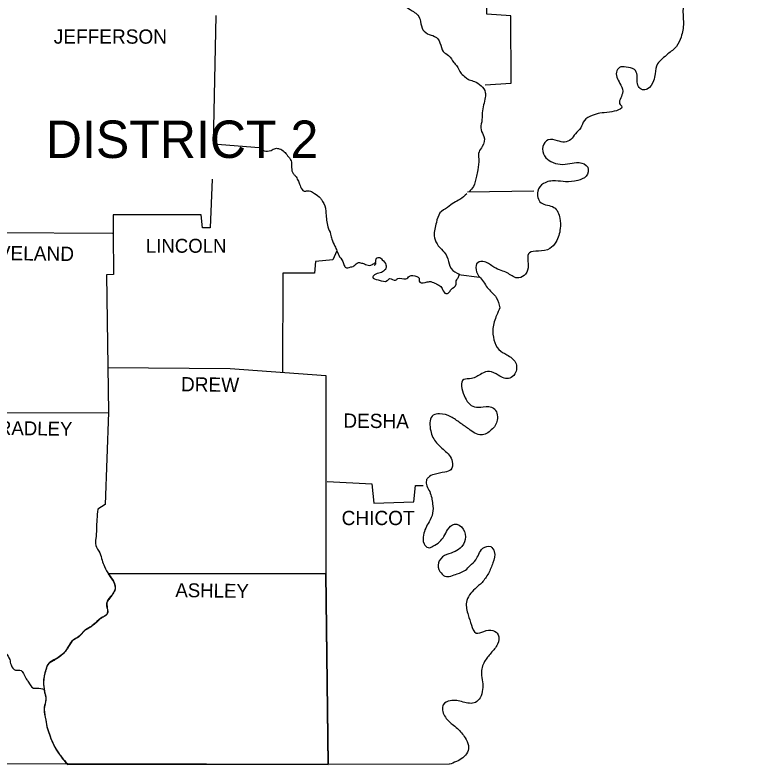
# Model space of a CAD drawing. Extents: x -42408 to 34530, y -43140 to 20491.
# Drawn here: x 3107 to 4217, y -9853 to -8719 of the extents above; entities that cross this region are included whole.
import ezdxf

# ---------------------------------------------------------------- set-up
doc = ezdxf.new("R2010")
doc.units = 0
for name, color, linetype in [('1', 7, 'Continuous'), ('2', 7, 'Continuous'), ('3', 7, 'Continuous'), ('S_MISC_BOUNDARY', 7, 'Continuous')]:
    doc.layers.add(name, color=color, linetype=linetype)

msp = doc.modelspace()

# ---------------------------------------------------------------- linework, layer by layer
at = {"layer": '1'}
msp.add_line((3791, -8986.4), (3891.1, -8984.9), dxfattribs=at)
for points in [[(3818, -8824.6), (3857.1, -8822.1), (3856.6, -8720.5), (3820.1, -8718), (3822.1, -8519.2), (3790.5, -8514.7), (3789.5, -8381), (4216.6, -8378)], [(3410.5, -8720), (3406.5, -8913.8), (3476.1, -8919.3)], [(3405, -8967.3), (3402, -9040.9), (3390.5, -9040.9), (3388.5, -9021.4), (3255.3, -9021.4), (3255.3, -9049.4)], [(3077.1, -9047.9), (3254.3, -9048.9)], [(3255.3, -9048.9), (3255.8, -9111.5), (3245.3, -9112), (3248.3, -9319.8)], [(3593.7, -9075.5), (3587.7, -9089), (3561.2, -9091.5), (3559.7, -9109.5), (3512.1, -9109.5), (3511.6, -9259.2)], [(3649.8, -9097.5), (3651.3, -9096), (3652.8, -9094.5), (3652.8, -9094.5)], [(3246.8, -9251.7), (3432.5, -9253.2), (3576.7, -9264.2)], [(3576.7, -9264.2), (3576.7, -9563.6), (3580.7, -9851.5)], [(3022, -9320.3), (3248.3, -9319.8)], [(3248.3, -9319.8), (3243.3, -9459), (3232.3, -9466)], [(3579.2, -9423.9), (3646.3, -9427.9), (3649.3, -9457), (3709.9, -9455), (3712.4, -9430.4), (3723.9, -9430.4)], [(1927.5, -9443.5), (1928.5, -9848.5), (3763.5, -9851.5)], [(3251.3, -9563.1), (3576.7, -9563.1)]]:
    msp.add_lwpolyline(points, dxfattribs=at)
for points in [[(4185, -8499.2), (4173.5, -8513.7), (4156.5, -8504.7), (4156.5, -8492.7), (4159, -8480.2), (4153, -8472.2), (4142.5, -8475.7), (4142.5, -8491.2), (4141.5, -8506.2), (4138.5, -8527.7), (4145.5, -8534.3), (4161.5, -8536.3), (4173, -8539.3), (4180, -8550.8), (4179.5, -8564.8), (4174, -8578.3), (4166, -8589.3), (4153.5, -8593.3), (4143.5, -8586.8), (4139.5, -8573.8), (4135, -8562.3), (4126.5, -8553.8), (4117.4, -8563.3), (4115.4, -8580.8), (4115.9, -8595.8), (4115.9, -8616.4), (4129, -8629.9), (4137, -8645.4), (4134.5, -8659.4), (4125, -8675.9), (4121, -8690.5), (4116.9, -8710), (4117.4, -8731.5), (4113.9, -8752.5), (4106.9, -8766.6), (4093.9, -8778.1), (4085.4, -8785.6), (4078.4, -8793.1), (4074.9, -8808.1), (4072.4, -8818.6), (4062.9, -8831.1), (4055.4, -8832.2), (4049.4, -8827.1), (4047.4, -8818.6), (4047.4, -8810.1), (4043.3, -8801.6), (4030.8, -8798.1), (4020.8, -8798.6), (4016.3, -8805.6), (4022.8, -8825.1), (4025.3, -8837.7), (4021.8, -8854.7), (4023.8, -8856.7), (4005.8, -8866.2), (3991.3, -8867.7), (3979.3, -8871.2), (3967.7, -8878.7), (3962.2, -8889.7), (3954.2, -8898.7), (3947.2, -8907.3), (3937.7, -8911.3), (3927.2, -8909.3), (3913.2, -8907.8), (3905.2, -8917.8), (3907.7, -8932.3), (3917.2, -8940.8), (3931.2, -8944.8), (3945.7, -8943.8), (3959.7, -8942.3), (3972.8, -8949.3), (3970.3, -8962.8), (3957.7, -8969.3), (3939.2, -8971.3), (3924.2, -8969.8), (3906.2, -8973.8), (3897.2, -8985.4), (3902.2, -9002.9), (3921.7, -9009.9), (3930.7, -9026.4), (3931.2, -9041.9), (3924.7, -9062.5), (3915.7, -9072), (3898.2, -9076), (3884.6, -9078.5), (3882.6, -9101.5), (3876.6, -9113), (3866.1, -9116.5), (3851.1, -9109), (3842.1, -9105.5), (3831.1, -9100.5), (3817, -9092), (3806.5, -9093.5), (3809.5, -9115.5), (3810.5, -9116.5), (3822.6, -9133.1), (3834.6, -9146.1), (3840.1, -9161.6)], [(3666.3, -8660.4), (3667.8, -8680.9), (3679.9, -8684), (3684.9, -8689.5), (3687.4, -8701), (3695.9, -8706), (3707.4, -8713), (3714.4, -8718), (3719.4, -8726), (3722.4, -8739), (3730.4, -8747.5), (3741.4, -8751.5), (3749.5, -8761.1), (3754.5, -8774.6), (3762.5, -8780.6), (3770.5, -8791.1), (3774.5, -8795.6), (3781.5, -8807.6), (3788.5, -8813.6), (3793.5, -8817.1), (3801.5, -8819.6), (3811.5, -8826.1), (3818, -8836.2), (3818, -8843.7), (3815.5, -8855.2), (3813.5, -8867.2), (3812.5, -8880.7), (3811.5, -8892.7), (3816, -8902.7), (3813.5, -8917.8), (3808.5, -8925.8), (3808, -8936.8), (3806.5, -8953.3), (3804.5, -8962.8), (3800, -8978.3), (3793.5, -8986.4)], [(3476.1, -8919.3), (3483.6, -8924.3), (3494.1, -8923.8), (3501.1, -8920.8), (3506.6, -8921.3), (3514.1, -8925.8), (3519.2, -8931.8), (3522.7, -8936.3), (3525.2, -8943.3), (3525.2, -8949.8), (3527.7, -8958.8), (3530.7, -8962.3), (3534.7, -8968.8), (3537.2, -8974.8), (3538.7, -8978.8), (3544.2, -8985.4), (3549.2, -8984.9), (3553.7, -8985.4), (3559.7, -8988.9), (3568.7, -8995.9), (3570.2, -8997.9), (3576.2, -9010.9), (3577.2, -9018.9), (3578.2, -9029.4), (3580.2, -9039.4), (3584.2, -9050.4), (3586.2, -9058), (3590.7, -9068.5), (3593.7, -9075.5), (3597.8, -9084.5), (3603.8, -9094.5), (3606.3, -9100.5), (3614.8, -9100), (3620.8, -9097.5), (3625.3, -9093.5), (3630.8, -9094), (3636.8, -9096), (3644.8, -9097.5), (3649.8, -9094.5), (3652.3, -9092.5), (3652.8, -9088), (3657.3, -9085.5), (3662.3, -9089), (3667.8, -9097), (3667.8, -9102), (3665.8, -9105), (3659.3, -9109), (3650.3, -9112), (3647.8, -9115.5), (3656.3, -9119.5), (3669.9, -9120.5), (3673.4, -9117.5), (3682.4, -9120), (3685.9, -9117.5), (3697.9, -9118), (3703.4, -9114), (3714.4, -9114.5), (3717.9, -9117), (3717.9, -9121.5), (3726.9, -9123.5), (3733.4, -9122), (3741.9, -9124.5), (3749.5, -9128.5), (3753.5, -9134.1), (3758.5, -9140.1), (3763, -9138.6), (3766.5, -9134.1), (3774, -9126), (3774, -9121), (3776, -9117.5), (3778.5, -9112.5)], [(3790, -8989.4), (3779.5, -8997.9), (3770.5, -9002.9), (3761, -9009.9), (3749.5, -9018.4), (3744, -9032.9), (3740.9, -9052.9), (3745, -9065), (3754, -9075.5), (3760, -9084), (3764.5, -9099), (3775.5, -9109.5), (3779, -9111)], [(3840.1, -9161.6), (3835.1, -9173.1), (3829.6, -9193.1), (3831.1, -9210.2), (3838.6, -9224.7), (3850.6, -9232.7), (3863.6, -9244.2), (3862.6, -9261.7), (3855.1, -9268.2), (3837.6, -9263.7), (3824.1, -9257.7), (3812.5, -9261.2), (3797, -9268.7), (3785.5, -9270.2), (3786, -9294.3), (3801.5, -9311.3), (3815, -9311.3), (3830.6, -9313.3), (3836.1, -9331.3), (3827.1, -9346.3), (3812, -9353.8), (3793, -9344.8), (3779.5, -9335.3), (3766, -9326.3), (3749, -9321.8), (3739.4, -9323.8), (3734.9, -9344.8), (3742.9, -9363.9), (3756, -9376.9), (3768, -9393.9), (3766, -9406.4), (3757, -9409.9), (3740.9, -9413.4), (3731.4, -9418.4), (3728.9, -9422.4), (3733.9, -9439.5), (3738.4, -9458), (3738.4, -9472), (3732.9, -9485), (3724.4, -9505), (3725.4, -9518.1), (3731.4, -9524.1), (3738.9, -9522.1), (3749, -9515.1), (3755.5, -9507.1), (3761, -9497), (3771.5, -9488.5), (3784.5, -9496), (3787.5, -9511.6), (3780, -9525.1), (3769.5, -9531.1), (3756.5, -9536.1), (3747, -9547.1), (3749.5, -9560.1), (3757, -9567.1), (3775.5, -9563.6), (3788, -9558.1), (3795, -9551.1), (3803.5, -9542.6), (3808, -9534.1), (3814.5, -9525.1), (3826.1, -9522.6), (3831.6, -9530.1), (3829.6, -9547.1), (3822.6, -9563.1), (3813, -9576.6), (3802.5, -9586.2), (3789.5, -9606.7), (3792, -9625.7), (3797, -9641.2), (3804, -9653.2), (3816, -9650.7), (3829.6, -9649.2), (3837.6, -9655.7), (3836.6, -9669.8), (3826.6, -9683.3), (3817, -9696.3), (3812, -9714.3), (3814, -9726.8), (3814, -9738.4), (3810, -9750.9), (3803, -9757.9), (3784.5, -9757.4), (3765, -9755.4), (3754.5, -9761.4), (3756.5, -9778.4), (3768, -9790.9), (3776, -9797.4), (3787.5, -9811.5), (3792.5, -9823), (3791, -9833), (3784, -9841.5), (3763.5, -9851.5)], [(3232.3, -9466), (3230.8, -9481.5), (3230.3, -9496), (3229.3, -9510.1), (3229.3, -9520.6), (3235.3, -9532.1), (3238.8, -9543.1), (3242.3, -9552.6), (3249.3, -9565.1), (3255.8, -9574.6), (3257.8, -9588.2), (3253.8, -9595.2), (3246.3, -9605.7), (3245.8, -9624.7), (3236.8, -9630.7), (3225.3, -9640.7), (3218.7, -9645.2), (3211.7, -9649.7), (3204.2, -9657.8), (3193.2, -9665.3), (3185.2, -9677.8), (3176.2, -9687.3), (3168.7, -9692.3), (3158.2, -9698.8), (3153.7, -9708.8), (3150.2, -9727.3), (3151.7, -9740.9), (3153.7, -9752.9), (3151.2, -9767.9), (3153.7, -9784.4), (3156.2, -9797.4), (3160.2, -9809), (3165.7, -9822), (3172.7, -9834), (3187.7, -9852.5)], [(2733.1, -9581.6), (2741.1, -9576.1), (2748.6, -9573.1), (2756.1, -9574.6), (2764.1, -9575.6), (2771.2, -9574.6), (2780.2, -9576.1), (2787.7, -9580.6), (2796.2, -9584.2), (2804.7, -9584.2), (2812.2, -9584.2), (2818.7, -9588.7), (2830.7, -9588.2), (2840.7, -9584.2), (2850.8, -9581.1), (2864.3, -9579.6), (2876.3, -9588.2), (2884.8, -9595.2), (2891.8, -9603.2), (2896.8, -9612.2), (2902.3, -9617.2), (2911.3, -9620.7), (2918.3, -9622.2), (2926.9, -9624.7), (2931.4, -9626.7), (2935.4, -9636.2), (2941.9, -9649.2), (2954.4, -9653.7), (2969.9, -9647.7), (2982.4, -9644.2), (2991.4, -9641.2), (2997, -9639.2), (3002, -9638.7), (3000.5, -9637.7), (3006.5, -9636.2), (3012, -9640.2), (3015.5, -9645.7), (3021.5, -9653.7), (3027, -9660.8), (3032.5, -9663.3), (3038, -9660.3), (3045.5, -9662.8), (3052, -9665.3), (3059.5, -9667.3), (3066, -9667.8), (3074.6, -9669.8), (3081.1, -9673.3), (3087.1, -9676.8), (3093.1, -9683.3), (3099.1, -9693.3), (3101.1, -9701.3), (3108.1, -9709.3), (3114.6, -9709.3), (3124.1, -9722.3), (3127.6, -9727.3), (3135.1, -9736.4), (3140.6, -9736.4), (3151.2, -9738.4)]]:
    msp.add_spline(points, degree=3, dxfattribs=at)
at = {"layer": '3'}
msp.add_line((3777.5, -9111.5), (3809, -9115.5), dxfattribs=at)
at = {"layer": 'S_MISC_BOUNDARY'}
for p, q in [((3576.7, -9563.6), (3248, -9563.6)), ((3580.7, -9851.7), (3576.7, -9563.6)), ((3185.9, -9851.1), (3580.7, -9851.7))]:
    msp.add_line(p, q, dxfattribs=at)
for points in [[(3248, -9563.6), (3249.3, -9565.6), (3250.9, -9568), (3252.5, -9570.4), (3254.2, -9572.7), (3255.8, -9575.1), (3258.4, -9581.9), (3258.6, -9585.4), (3257.8, -9588.7), (3253.8, -9595.7), (3252, -9598.3), (3250, -9600.9), (3248.1, -9603.5), (3246.3, -9606.2), (3245.5, -9610.8), (3246.5, -9616), (3247.4, -9621.1), (3245.8, -9625.2), (3244.8, -9626.1), (3243.7, -9626.9), (3241.3, -9628.3), (3239, -9629.7), (3236.8, -9631.2), (3231.1, -9636.3), (3228.3, -9638.9), (3225.3, -9641.2), (3218.8, -9645.7), (3211.7, -9650.2), (3209.7, -9652), (3208.3, -9653.6)], [(3208.3, -9653.6), (3207.9, -9654.1), (3206.1, -9656.3), (3204.2, -9658.3), (3201.6, -9660.2), (3198.6, -9661.9), (3195.8, -9663.6), (3193.2, -9665.8), (3191, -9668.7), (3189.1, -9671.9), (3187.3, -9675.2), (3185.2, -9678.3), (3183.1, -9680.8), (3181, -9683.3), (3176.2, -9687.8), (3168.7, -9692.8), (3166.1, -9694.4), (3163.4, -9695.9), (3159.5, -9698.4), (3158.2, -9699.3), (3156.4, -9701.4), (3155.2, -9703.8), (3153.7, -9709.3), (3152.3, -9713.9), (3151.1, -9718.6), (3150.3, -9723.2), (3150.2, -9727.8), (3150.8, -9734.6), (3151.7, -9741.4), (3152.2, -9744.5)], [(3152.2, -9744.5), (3153.7, -9753.4), (3153.4, -9757.1), (3152.4, -9760.9), (3151.4, -9764.6), (3151.2, -9768.4), (3153.7, -9784.9), (3156.2, -9797.9), (3160.2, -9809.5), (3165.7, -9822.5), (3169, -9828.6), (3172.7, -9834.5), (3179, -9843), (3185.9, -9851.1)]]:
    msp.add_spline(points, degree=3, dxfattribs=at)

# ---------------------------------------------------------------- texts
at = {"layer": '2'}
for s, height, p in [('JEFFERSON', 21.53, (3165.7, -8762.6)), ('LINCOLN', 21.03, (3304.9, -9078.5)), ('CHICOT', 21.53, (3600.8, -9490))]:
    msp.add_text(s, height=height, dxfattribs=at).set_placement(p)
for s, height, rotation, p in [('CLEVELAND', 21.53, 359.3377, (3025, -9089)), ('DREW', 21.52, 359.2258, (3357.9, -9287.8)), ('DESHA', 21.52, 359.3704, (3603.3, -9342.8)), ('BRADLEY', 21.02, 359.1449, (3062.5, -9353.3)), ('ASHLEY', 21.03, 359.2361, (3349.4, -9598.7))]:
    msp.add_text(s, height=height, rotation=rotation, dxfattribs=at).set_placement(p)
at = {"layer": '3'}
msp.add_text('DISTRICT 2', height=56.57, dxfattribs=at).set_placement((3153.7, -8935.3))

doc.saveas('drawing.dxf')
